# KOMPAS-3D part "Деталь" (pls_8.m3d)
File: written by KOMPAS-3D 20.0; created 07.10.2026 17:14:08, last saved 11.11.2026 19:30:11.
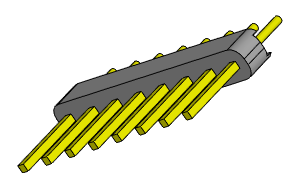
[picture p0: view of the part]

Document properties: Полное имя файла: D:\myProjects\Progect_esp32\box_compas\разъемы\pls_8.m3d

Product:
- Part/product: Деталь
    Масса: 0.00102673

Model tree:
1. Эскиз:1
2. Элемент выдавливания:1
     Расстояние 1 = 2.5
3. Эскиз:2  (with: Элемент выдавливания:1)
4. Элемент выдавливания:2
     Расстояние 1 = 6
5. Массив по сетке:1  (with: Элемент выдавливания:2, Эскиз:2)  (8 pattern instances)
     Шаг 1 = 2.54; Угол раствора = 90
6. Эскиз:3  (with: Элемент выдавливания:1)
7. Элемент выдавливания:3
     Расстояние 1 = 3
8. Массив по сетке:2  (with: Элемент выдавливания:3, Эскиз:3)  (8 pattern instances)
     Шаг 1 = 2.54; Угол раствора = 90; Геометрический массив = 128
9. Эскиз:4  (with: Элемент выдавливания:1)
10. Элемент выдавливания:4
     Расстояние 2 = 20.32
11. Скругление:1  (with: Элемент выдавливания:1)
     Радиус = 1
